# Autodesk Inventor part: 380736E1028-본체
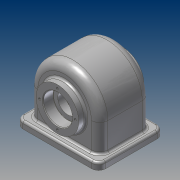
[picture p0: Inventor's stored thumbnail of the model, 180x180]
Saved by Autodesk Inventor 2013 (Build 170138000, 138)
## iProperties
Created: 2018-07
Part Number: 380736E1028-본체
Material: 강철, 연질 7g
Document SubType Name: Modeling
Designer: 05-01
Density: 7 g/cm^3
Mass: 2599.41 g
Surface Area: 808.177 cm^2
Volume: 371.344 cm^3
Author: 05-01
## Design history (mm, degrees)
sketch "스케치1"
  geometry: L1 (-51, -40)-(-51, 0); L2 (51, -40)-(-51, -40); L3 (51, 0)-(51, -40); A1 r 51 centre (0, 0) between (51, 0) and (-51, 0); 1 further point
  constraints: 6 end point, 2 point on circle, 2 tangent, 1 centre point, 1 coincident, 1 parallel, 1 perpendicular, 1 vertical
  dimensions: "d0" = 51 radius of A1; "d3" = 40 distance from line of L2 point (0, 0)
extrude "돌출1" new body sketch "스케치1" stored distance "d4" = 74; taper "d5" = 0 deg
fillet "모깎기1" dims "d6" = 12
feature "쉘1" dims "d7" = 9
sketch "스케치2"
  geometry: L1 (0, -9)-(78, -9) reference; L2 (-3, -62)-(-3, -12) reference; L3 (78, -65)-(0, -65) reference; L4 (81, -12)-(81, -62) reference; L5 (-21, -84.5)-(99, -84.5); L6 (99, -84.5)-(99, 10.5); L7 (99, 10.5)-(-21, 10.5); L8 (-21, 10.5)-(-21, -84.5); L9 (-21, -84.5)-(99, 10.5); L10 (99, -84.5)-(-21, 10.5); A1 r 3 centre (0, -12) between (0, -9) and (-3, -12) reference; A2 r 3 centre (0, -62) between (-3, -62) and (0, -65) reference; A3 r 3 centre (78, -62) between (78, -65) and (81, -62) reference; A4 r 3 centre (78, -12) between (81, -12) and (78, -9) reference; 1 further point
  constraints: 12 end point, 2 midpoint, 2 parallel, 1 horizontal, 1 perpendicular
  dimensions: "d8" = 120 distance of L6.end L7.end; "d10" = 95 distance of L5.end L6.end
extrude "돌출2" join sketch "스케치2" distance "d11" = 10; taper "d12" = 0 deg
fillet "모깎기2" dims "d13" = 10
sketch "스케치3"
  geometry: 1 further point
sketch "스케치4"
  geometry: C1 r 31 at (0, 0); 1 further point
  constraints: 1 centre point, 1 coincident
  dimensions: "d14" = 62 diameter of C1
extrude "돌출3" join sketch "스케치4" distance "d15" = 10.4; taper "d16" = 0 deg
sketch "스케치5"
  geometry: C1 r 31 at (0, 0); 1 further point
  constraints: 1 centre point, 1 coincident
  dimensions: "d17" = 62 diameter of C1
extrude "돌출4" join sketch "스케치5" distance "d20" = 6; taper "d21" = 0 deg
hole "구멍1" diameter "d24" = 29; stored, may be unused: countersink angle "d28" = 90 deg, drill point angle "d30" = 0 deg; dims "d25" = 6, "d26" = 35, "d27" = 15, "d29" = 8, "d33" = 10, "d34" = 10
fillet "모깎기3" dims "d31" = 3
sketch "스케치6"
  geometry: 2 further points
  constraints: 1 vertical alignment
  dimensions: "d32" = 26 distance of point (0, 0) point (0, 26)
hole "구멍2" sketch "스케치6" at (0, 26) diameter "d35" = 3.242; stored, may be unused: countersink angle "d39" = 90 deg, drill point angle "d41" = 118 deg; dims "d36" = 11, "d37" = 4, "d38" = 2, "d40" = 14
fillet "모깎기4" dims "d45" = 0.3
chamfer "모따기1" distance "d46" = 1; stored, may be unused: second distance "d47" = 2, angle "d48" = 45 deg
hole "구멍3" diameter "d51" = 42; stored, may be unused: countersink angle "d55" = 90 deg, drill point angle "d57" = 0 deg; dims "d49" = 10, "d50" = 10, "d52" = 3, "d53" = 4, "d54" = 2, "d56" = 15
fillet "모깎기5" dims "d58" = 0.3
chamfer "모따기2" distance "d59" = 1; stored, may be unused: second distance "d60" = 2, angle "d61" = 45 deg
node "솔리드1"
mirror "대칭1"
pattern_circular "원형 패턴1" dims angle "d43" = 360 deg
mirror "대칭2"
